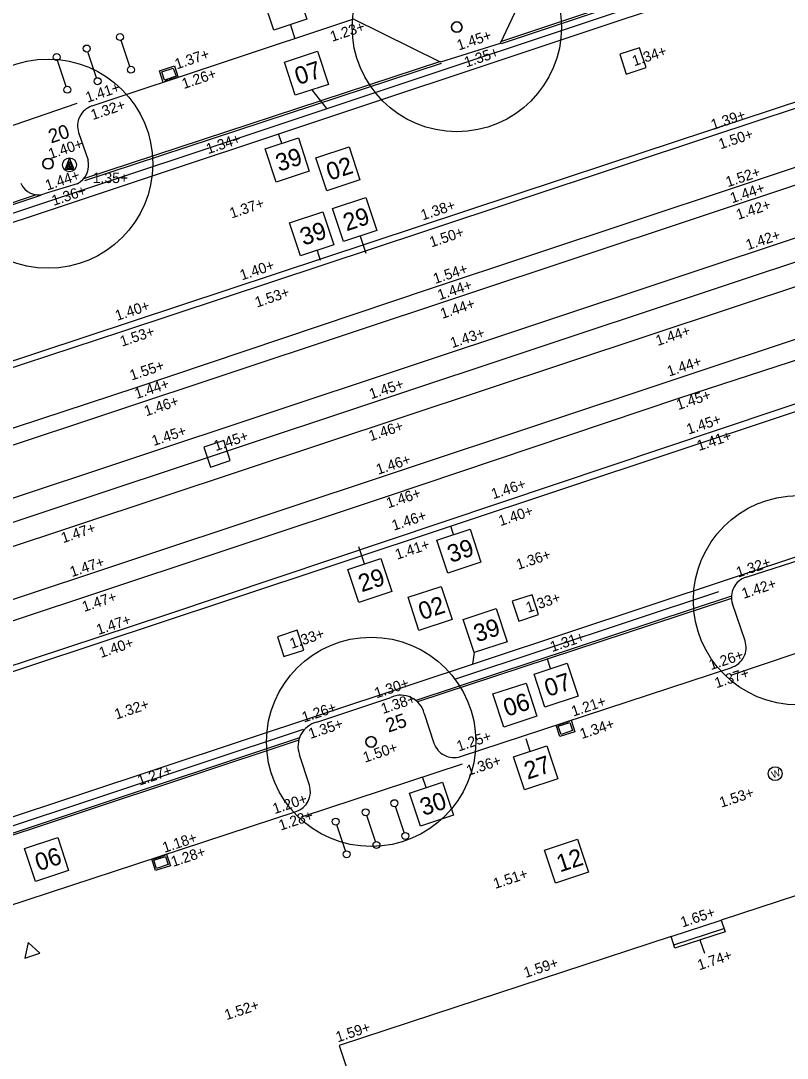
# Model space of a CAD drawing. Extents: x 122462 to 123306, y 485548 to 486417.
# Drawn here: x 122736.78 to 122758.75, y 486138.24 to 486167.98 of the extents above; entities that cross this region are included whole.
import ezdxf

# ---------------------------------------------------------------- set-up
doc = ezdxf.new("R2010")
doc.units = 0
for name, color, linetype in [('B-WE-GR-BOOM_BOOMDIAMETER', 7, 'Continuous'), ('B-WE-OG-HOOGTEPUNT-S', 7, 'Continuous'), ('B-WE-OG-TOPOGRAFIE_GEVELDETAIL-G', 7, 'Continuous'), ('B-WE-OG-TOPOKAART-G', 7, 'Continuous'), ('iba7-verkeersbord blauw', 7, 'Continuous'), ('iba7-verkeersbord rood', 7, 'Continuous'), ('V markering 1-1 10 cm', 7, 'Continuous'), ('V markering figuratie', 7, 'Continuous'), ('V markering ononderbroken streep 10 cm', 7, 'Continuous'), ('V materiaalscheiding algemeen', 7, 'Continuous'), ('V meubilair fietsenrek', 7, 'Continuous'), ('V meubilair trammast', 7, 'Continuous'), ('V meubilair verkeersbord', 7, 'Continuous'), ('V opsluitband 100x200 mm', 7, 'Continuous'), ('V Rails', 7, 'Continuous'), ('V riool putdeksel', 7, 'Continuous'), ('V riool trottoirkolk', 7, 'Continuous'), ('V RWS-band 115-225x250 mm specie', 7, 'Continuous'), ('V trottoirband 180-200x250 mm specie', 7, 'Continuous'), ('X-WE-AL-TEKENBLAD-S', 7, 'Continuous')]:
    doc.layers.add(name, color=color, linetype=linetype)

msp = doc.modelspace()

# ---------------------------------------------------------------- linework, layer by layer
at = {"layer": 'B-WE-OG-TOPOGRAFIE_GEVELDETAIL-G'}
for p, q in [((122755.498, 486141.492), (122756.934, 486141.963)), ((122756.247, 486141.632), (122756.372, 486141.253))]:
    msp.add_line(p, q, dxfattribs=at)
msp.add_lwpolyline([(122755.42, 486141.73), (122756.855, 486142.201), (122756.965, 486141.868), (122755.529, 486141.397)], close=True, dxfattribs=at)
at = {"layer": 'B-WE-OG-TOPOKAART-G'}
for points in [[(122759.037, 486142.916), (122756.856, 486142.201)], [(122755.42, 486141.73), (122749.252, 486139.707), (122745.91, 486138.61), (122746.866, 486135.726), (122744.974, 486135.1)]]:
    msp.add_lwpolyline(points, dxfattribs=at)
at = {"layer": 'iba7-verkeersbord blauw'}
msp.add_circle((122758.4, 486146.399), 0.2, dxfattribs=at)
at = {"layer": 'iba7-verkeersbord rood'}
for centre, radius in [((122749.278, 486167.803), 3), ((122749.278, 486167.803), 0.15), ((122737.564, 486163.887), 3), ((122737.564, 486163.887), 0.15), ((122759.058, 486151.369), 3), ((122746.823, 486147.311), 3), ((122746.823, 486147.311), 0.15)]:
    msp.add_circle(centre, radius, dxfattribs=at)
for centre, start, end in [((122749.278, 486167.803), 0, 180), ((122749.278, 486167.803), 180, 0), ((122737.564, 486163.887), 0, 180), ((122737.564, 486163.887), 180, 0), ((122746.823, 486147.311), 0, 180), ((122746.823, 486147.311), 180, 0)]:
    msp.add_arc(centre, 0.15, start, end, dxfattribs=at)
at = {"layer": 'V markering 1-1 10 cm'}
for p, q in [((122774.598, 486175.14), (122727.918, 486159.59)), ((122732.076, 486143.681), (122790.419, 486163.059)), ((122749.252, 486149.122), (122756.783, 486151.623)), ((122732.154, 486143.443), (122744.883, 486147.671))]:
    msp.add_line(p, q, dxfattribs=at)
msp.add_lwpolyline([(122774.677, 486174.903), (122727.997, 486159.353)], dxfattribs=at)
at = {"layer": 'V markering figuratie'}
msp.add_line((122712.845, 486143.511), (122860.885, 486192.728), dxfattribs=at)
at = {"layer": 'V markering ononderbroken streep 10 cm'}
for p, q in [((122761.511, 486171.05), (122750.527, 486167.381)), ((122748.806, 486166.818), (122738.581, 486163.449)), ((122737.222, 486162.996), (122727.575, 486159.765)), ((122757.15, 486151.423), (122748.155, 486148.454))]:
    msp.add_line(p, q, dxfattribs=at)
for points in [[(122782.506, 486173.456), (122769.669, 486169.188), (122753.621, 486163.883), (122729.113, 486155.773)], [(122728.941, 486151.077), (122760.57, 486161.6), (122777.147, 486167.134), (122788.89, 486171.042)], [(122790.431, 486167.268), (122783.519, 486164.927), (122758.686, 486156.675), (122742.703, 486151.362), (122729.592, 486147.018)], [(122744.749, 486147.36), (122732.209, 486143.188)]]:
    msp.add_lwpolyline(points, dxfattribs=at)
at = {"layer": 'V materiaalscheiding algemeen'}
for points in [[(122761.53, 486170.993), (122750.546, 486167.324)], [(122748.825, 486166.761), (122738.611, 486163.396)], [(122780.156, 486165.287), (122764.259, 486160.016), (122760.446, 486158.724), (122755.663, 486157.161), (122747.256, 486154.337), (122738.577, 486151.45), (122730.117, 486148.653), (122721.549, 486145.803), (122712.998, 486142.94), (122707.935, 486141.266)], [(122737.346, 486162.974), (122727.454, 486159.661)], [(122757.15, 486151.486), (122748.103, 486148.5)], [(122757.129, 486149.222), (122763.738, 486151.452)], [(122744.769, 486147.43), (122732.216, 486143.253), (122732.207, 486143.158)], [(122744.83, 486145.158), (122749.439, 486146.684)]]:
    msp.add_lwpolyline(points, dxfattribs=at)
at = {"layer": 'V meubilair fietsenrek'}
for p, q in [((122739.907, 486166.676), (122739.659, 486167.422)), ((122738.086, 486166.102), (122737.838, 486166.848)), ((122738.951, 486166.347), (122738.703, 486167.093)), ((122747.769, 486144.71), (122747.521, 486145.457)), ((122746.945, 486144.45), (122746.698, 486145.197)), ((122746.087, 486144.183), (122745.839, 486144.929))]:
    msp.add_line(p, q, dxfattribs=at)
for centre in [(122739.628, 486167.517), (122738.672, 486167.188), (122737.807, 486166.943), (122739.938, 486166.581), (122738.982, 486166.252), (122738.117, 486166.007), (122747.49, 486145.552), (122745.808, 486145.024), (122746.666, 486145.292), (122747.8, 486144.615), (122746.976, 486144.355), (122746.118, 486144.088)]:
    msp.add_circle(centre, 0.1, dxfattribs=at)
at = {"layer": 'V meubilair trammast'}
msp.add_lwpolyline([(122736.901, 486141.114), (122737.328, 486141.255), (122736.992, 486141.555)], close=True, dxfattribs=at)
at = {"layer": 'V meubilair verkeersbord'}
msp.add_lwpolyline([(122738.304, 486163.717), (122738.052, 486163.717), (122738.179, 486164.04), (122738.293, 486163.755), (122738.108, 486163.755), (122738.179, 486163.955), (122738.235, 486163.795), (122738.166, 486163.795), (122738.179, 486163.835), (122738.18, 486163.885)], dxfattribs=at)
msp.add_circle((122738.179, 486163.855), 0.2, dxfattribs=at)
at = {"layer": 'V opsluitband 100x200 mm'}
msp.add_lwpolyline([(122736.032, 486164.805), (122738.398, 486165.618)], dxfattribs=at)
at = {"layer": 'V Rails'}
for p, q in [((122714.919, 486148.627), (122859.557, 486196.72)), ((122715.373, 486147.26), (122860.011, 486195.354)), ((122712.39, 486144.878), (122860.43, 486194.095))]:
    msp.add_line(p, q, dxfattribs=at)
at = {"layer": 'V riool putdeksel'}
for points in [[(122753.947, 486167.024), (122754.135, 486166.454), (122754.705, 486166.642), (122754.517, 486167.212)], [(122742.029, 486155.76), (122742.217, 486155.19), (122742.787, 486155.377), (122742.599, 486155.947)], [(122751.053, 486150.77), (122751.623, 486150.958), (122751.435, 486151.528), (122750.865, 486151.34)], [(122744.324, 486149.756), (122744.894, 486149.944), (122744.706, 486150.514), (122744.136, 486150.326)]]:
    msp.add_lwpolyline(points, close=True, dxfattribs=at)
at = {"layer": 'V riool trottoirkolk'}
for p, q in [((122740.757, 486166.551), (122741.184, 486166.692)), ((122740.867, 486166.218), (122740.757, 486166.551)), ((122741.184, 486166.692), (122741.294, 486166.36)), ((122741.294, 486166.36), (122740.867, 486166.218)), ((122740.914, 486166.234), (122740.913, 486166.239)), ((122740.995, 486166.277), (122740.919, 486166.251)), ((122741.009, 486166.266), (122741.008, 486166.27)), ((122741.033, 486166.273), (122741.031, 486166.278)), ((122741.114, 486166.316), (122741.038, 486166.291)), ((122741.128, 486166.305), (122741.126, 486166.31)), ((122741.152, 486166.313), (122741.15, 486166.317)), ((122741.188, 486166.34), (122741.156, 486166.33)), ((122741.232, 486166.355), (122741.188, 486166.34)), ((122741.247, 486166.344), (122741.245, 486166.349)), ((122752.124, 486147.792), (122752.551, 486147.933)), ((122752.171, 486147.808), (122752.173, 486147.803)), ((122752.185, 486147.797), (122752.23, 486147.811)), ((122752.23, 486147.811), (122752.261, 486147.822)), ((122752.266, 486147.839), (122752.268, 486147.834)), ((122752.29, 486147.847), (122752.292, 486147.842)), ((122752.304, 486147.836), (122752.38, 486147.861)), ((122752.385, 486147.878), (122752.387, 486147.873)), ((122752.409, 486147.886), (122752.41, 486147.881)), ((122752.423, 486147.875), (122752.499, 486147.9)), ((122752.504, 486147.917), (122752.505, 486147.912)), ((122752.551, 486147.933), (122752.661, 486147.6)), ((122752.233, 486147.46), (122752.124, 486147.792)), ((122752.661, 486147.6), (122752.233, 486147.46)), ((122740.534, 486143.951), (122740.962, 486144.091)), ((122740.643, 486143.618), (122740.534, 486143.951)), ((122740.582, 486143.966), (122740.583, 486143.961)), ((122740.596, 486143.955), (122740.641, 486143.97)), ((122740.641, 486143.97), (122740.672, 486143.98)), ((122740.677, 486143.997), (122740.678, 486143.993)), ((122740.701, 486144.005), (122740.702, 486144)), ((122740.715, 486143.994), (122740.791, 486144.019)), ((122740.796, 486144.036), (122740.797, 486144.031)), ((122740.819, 486144.044), (122740.821, 486144.039)), ((122740.833, 486144.033), (122740.91, 486144.058)), ((122740.914, 486144.075), (122740.916, 486144.07)), ((122740.962, 486144.091), (122741.071, 486143.758)), ((122741.071, 486143.758), (122740.643, 486143.618))]:
    msp.add_line(p, q, dxfattribs=at)
for points in [[(122740.82, 486166.519), (122741.152, 486166.629), (122741.231, 486166.392), (122740.899, 486166.282)], [(122752.597, 486147.632), (122752.265, 486147.523), (122752.187, 486147.76), (122752.519, 486147.87)], [(122741.008, 486143.79), (122740.675, 486143.681), (122740.597, 486143.919), (122740.93, 486144.028)]]:
    msp.add_lwpolyline(points, close=True, dxfattribs=at)
for centre, start, end in [((122740.922, 486166.242), 108.3322, 198.3322), ((122740.998, 486166.267), 18.3322, 108.3322), ((122741.041, 486166.281), 108.3322, 198.3322), ((122741.117, 486166.306), 18.3322, 108.3322), ((122741.16, 486166.321), 108.3322, 198.3322), ((122741.236, 486166.346), 18.3322, 108.3322), ((122752.182, 486147.806), 198.1886, 288.1886), ((122752.258, 486147.831), 288.1886, 18.1886), ((122752.301, 486147.845), 198.1886, 288.1886), ((122752.377, 486147.87), 288.1886, 18.1886), ((122752.42, 486147.884), 198.1886, 288.1886), ((122752.496, 486147.909), 288.1886, 18.1886), ((122740.593, 486143.965), 198.1247, 288.1247), ((122740.669, 486143.989), 288.1247, 18.1247), ((122740.712, 486144.003), 198.1247, 288.1247), ((122740.788, 486144.028), 288.1247, 18.1247), ((122740.83, 486144.042), 198.1247, 288.1247), ((122740.906, 486144.067), 288.1247, 18.1247)]:
    msp.add_arc(centre, 0.01, start, end, dxfattribs=at)
at = {"layer": 'V RWS-band 115-225x250 mm specie'}
msp.add_lwpolyline([(122788.059, 486166.632), (122787.124, 486166.306), (122785.206, 486165.623), (122777.128, 486162.968), (122760.015, 486157.342), (122740.955, 486150.951), (122719.987, 486144.031), (122708.301, 486140.155)], dxfattribs=at)
at = {"layer": 'V trottoirband 180-200x250 mm specie'}
msp.add_line((122757.538, 486150.208), (122757.18, 486151.27), dxfattribs=at)
for points in [[(122802.843, 486178.897), (122803.005, 486178.403), (122796.653, 486176.321), (122790.145, 486174.137), (122787.981, 486173.414), (122783.643, 486171.985), (122782.562, 486171.633), (122774.188, 486168.85), (122765.631, 486166.001), (122757.287, 486163.217), (122748.482, 486160.287), (122740.076, 486157.459), (122731.818, 486154.747)], [(122772.234, 486176.591), (122764.613, 486174.078), (122763.348, 486171.596), (122761.53, 486170.993), (122760.929, 486172.847), (122759.643, 486172.424), (122751.679, 486169.79), (122750.518, 486167.331), (122748.806, 486166.796), (122746.321, 486168.026), (122738.818, 486165.54)], [(122731.297, 486156.319), (122739.679, 486159.075), (122748.36, 486161.956), (122756.611, 486164.69), (122764.995, 486167.464)], [(122738.439, 486164.777), (122738.709, 486163.983)], [(122738.402, 486163.308), (122737.452, 486163.018)], [(122757.567, 486152.034), (122759.417, 486152.622), (122761.652, 486153.364)], [(122749.383, 486146.892), (122757.155, 486149.446)], [(122745.268, 486147.876), (122747.383, 486148.585)], [(122748.346, 486148.122), (122748.622, 486147.275)], [(122745.052, 486146.07), (122744.767, 486146.939)], [(122733.81, 486141.749), (122740.748, 486144.02), (122744.67, 486145.313)]]:
    msp.add_lwpolyline(points, dxfattribs=at)
for centre, radius, start, end in [((122739.007, 486164.971), 0.6, 108.3322, 198.7713), ((122738.126, 486163.841), 0.6, 297.3747, 13.7118), ((122737.285, 486163.541), 0.549, 203.3042, 287.6664), ((122757.749, 486151.462), 0.6, 107.6439, 198.6036), ((122756.969, 486150.016), 0.6, 288.01, 18.6036), ((122747.674, 486147.957), 0.692, 13.8151, 114.8294), ((122745.444, 486147.18), 0.718, 104.1614, 199.5731), ((122749.193, 486147.461), 0.6, 198.0639, 288.4796), ((122744.482, 486145.883), 0.6, 288.2477, 18.1882)]:
    msp.add_arc(centre, radius, start, end, dxfattribs=at)
at = {"layer": 'X-WE-AL-TEKENBLAD-S'}
for p, q in [((122744.508, 486167.87), (122744.64, 486167.469)), ((122745.123, 486166.004), (122745.539, 486165.472)), ((122744.262, 486164.467), (122744.171, 486164.741)), ((122746.507, 486161.811), (122746.669, 486161.321)), ((122745.274, 486161.399), (122745.364, 486161.125)), ((122749.182, 486153.254), (122749.104, 486153.49)), ((122746.63, 486152.412), (122746.468, 486152.901)), ((122749.773, 486149.869), (122749.731, 486149.541)), ((122751.967, 486149.412), (122751.877, 486149.686)), ((122751.381, 486147.039), (122751.262, 486147.398)), ((122748.395, 486145.999), (122748.294, 486146.305))]:
    msp.add_line(p, q, dxfattribs=at)
for points in [[(122743.719, 486168.663), (122744.669, 486168.977), (122744.982, 486168.027), (122744.033, 486167.714)], [(122744.335, 486166.797), (122745.285, 486167.11), (122745.598, 486166.16), (122744.649, 486165.847)], [(122743.787, 486164.31), (122744.737, 486164.623), (122745.05, 486163.674), (122744.1, 486163.36)], [(122745.24, 486164.055), (122746.19, 486164.368), (122746.503, 486163.419), (122745.553, 486163.105)], [(122745.719, 486162.604), (122746.668, 486162.917), (122746.982, 486161.967), (122746.032, 486161.654)], [(122744.486, 486162.192), (122745.435, 486162.505), (122745.749, 486161.556), (122744.799, 486161.242)], [(122748.707, 486153.097), (122749.657, 486153.411), (122749.97, 486152.461), (122749.021, 486152.148)], [(122746.155, 486152.255), (122747.105, 486152.568), (122747.418, 486151.619), (122746.468, 486151.305)], [(122747.88, 486151.455), (122748.83, 486151.769), (122749.143, 486150.819), (122748.194, 486150.506)], [(122749.459, 486150.819), (122750.409, 486151.132), (122750.722, 486150.182), (122749.773, 486149.869)], [(122751.492, 486149.255), (122752.442, 486149.568), (122752.755, 486148.619), (122751.805, 486148.305)], [(122750.312, 486148.684), (122751.261, 486148.998), (122751.575, 486148.048), (122750.625, 486147.735)], [(122750.906, 486146.882), (122751.856, 486147.196), (122752.169, 486146.246), (122751.219, 486145.933)], [(122747.92, 486145.842), (122748.87, 486146.156), (122749.183, 486145.206), (122748.233, 486144.893)], [(122736.891, 486144.256), (122737.841, 486144.57), (122738.154, 486143.62), (122737.205, 486143.307)], [(122751.788, 486144.208), (122752.738, 486144.521), (122753.051, 486143.572), (122752.102, 486143.258)]]:
    msp.add_lwpolyline(points, close=True, dxfattribs=at)

# ---------------------------------------------------------------- texts
at = {"layer": 'B-WE-GR-BOOM_BOOMDIAMETER'}
for s, rotation, p in [('20', 18.3322, (122737.65, 486164.463)), ('25', 18.8399, (122747.318, 486147.573))]:
    msp.add_text(s, height=0.4, rotation=rotation, dxfattribs=at).set_placement(p)
at = {"layer": 'B-WE-OG-HOOGTEPUNT-S'}
for s, rotation, p in [('1.23+', 18.4074, (122745.706, 486167.378)), ('1.45+', 18.4074, (122749.338, 486167.13)), ('1.35+', 18.4074, (122749.547, 486166.642)), ('1.34+', 18.4074, (122754.36, 486166.678)), ('1.37+', 18.5166, (122741.254, 486166.589)), ('1.26+', 18.5166, (122741.455, 486166.026)), ('1.41+', 18.5166, (122738.696, 486165.634)), ('1.32+', 18.5166, (122738.845, 486165.134)), ('1.39+', 18.3718, (122756.617, 486164.85)), ('1.50+', 18.3718, (122756.838, 486164.297)), ('1.40+', 18.5166, (122737.631, 486164.016)), ('1.34+', 18.5166, (122742.152, 486164.158)), ('1.44+', 18.5166, (122737.541, 486163.115)), ('1.52+', 18.3429, (122757.044, 486163.21)), ('1.44+', 18.3429, (122757.168, 486162.75)), ('1.36+', 18.4074, (122737.726, 486162.676)), ('1.37+', 18.5166, (122742.824, 486162.313)), ('1.38+', 18.3718, (122748.302, 486162.26)), ('1.42+', 18.3429, (122757.342, 486162.275)), ('1.50+', 18.3718, (122748.55, 486161.485)), ('1.42+', 18.3429, (122757.619, 486161.405)), ('1.40+', 18.5166, (122743.118, 486160.538)), ('1.54+', 18.3718, (122748.657, 486160.436)), ('1.53+', 18.5166, (122743.551, 486159.761)), ('1.44+', 18.3718, (122748.784, 486159.971)), ('1.40+', 18.3718, (122739.543, 486159.378)), ('1.44+', 18.3718, (122748.863, 486159.435)), ('1.53+', 18.3718, (122739.682, 486158.639)), ('1.43+', 18.3718, (122749.147, 486158.597)), ('1.44+', 18.3429, (122755.036, 486158.66)), ('1.44+', 18.3429, (122755.36, 486157.781)), ('1.55+', 18.3718, (122739.96, 486157.667)), ('1.44+', 18.3718, (122740.102, 486157.137)), ('1.45+', 18.3718, (122746.825, 486157.132)), ('1.45+', 18.3429, (122755.625, 486156.821)), ('1.46+', 18.3718, (122740.375, 486156.642)), ('1.46+', 18.3718, (122746.81, 486155.929)), ('1.45+', 18.3429, (122755.919, 486156.119)), ('1.45+', 18.3718, (122740.592, 486155.789)), ('1.45+', 18.3718, (122742.37, 486155.643)), ('1.41+', 18.3429, (122756.216, 486155.647)), ('1.46+', 18.3718, (122747.023, 486154.968)), ('1.46+', 18.3738, (122750.323, 486154.266)), ('1.46+', 18.3718, (122747.314, 486154.003)), ('1.46+', 18.3718, (122747.473, 486153.362)), ('1.40+', 18.3738, (122750.529, 486153.494)), ('1.47+', 18.4023, (122737.994, 486153.005)), ('1.41+', 18.3718, (122747.568, 486152.53)), ('1.47+', 18.4023, (122738.246, 486152.032)), ('1.36+', 18.3738, (122751.038, 486152.242)), ('1.32+', 18.3738, (122757.341, 486152.018)), ('1.42+', 18.3738, (122757.501, 486151.41)), ('1.47+', 18.4023, (122738.596, 486151.033)), ('1.33+', 18.3738, (122751.315, 486151.01)), ('1.47+', 18.4023, (122739.006, 486150.374)), ('1.33+', 18.3738, (122744.547, 486149.975)), ('1.40+', 18.4023, (122739.08, 486149.714)), ('1.31+', 18.3738, (122752.009, 486149.883)), ('1.26+', 18.3738, (122756.56, 486149.365)), ('1.37+', 18.3738, (122756.723, 486148.846)), ('1.30+', 18.3738, (122746.975, 486148.556)), ('1.32+', 18.3738, (122739.525, 486147.95)), ('1.26+', 18.3738, (122744.896, 486147.863)), ('1.38+', 18.3738, (122747.162, 486148.109)), ('1.21+', 18.3738, (122752.617, 486148.034)), ('1.35+', 18.3738, (122745.083, 486147.392)), ('1.34+', 18.3738, (122752.862, 486147.389)), ('1.25+', 18.3738, (122749.332, 486147.033)), ('1.50+', 18.3738, (122746.646, 486146.713)), ('1.36+', 18.3738, (122749.611, 486146.334)), ('1.27+', 18.3738, (122740.183, 486146.053)), ('1.20+', 18.3738, (122744.057, 486145.239)), ('1.53+', 18.1571, (122756.858, 486145.421)), ('1.28+', 18.3738, (122744.23, 486144.763)), ('1.18+', 18.3738, (122740.898, 486144.126)), ('1.28+', 18.3738, (122741.144, 486143.723)), ('1.51+', 18.2074, (122750.379, 486143.093)), ('1.65+', 18.1571, (122755.746, 486141.988)), ('1.74+', 18.1571, (122756.231, 486140.76)), ('1.59+', 18.2074, (122751.252, 486140.541)), ('1.52+', 18.2074, (122742.679, 486139.33)), ('1.59+', 18.2074, (122745.866, 486138.694))]:
    msp.add_text(s, height=0.3, rotation=rotation, dxfattribs=at).set_placement(p)
msp.add_text('1.35+', height=0.3, dxfattribs=at).set_placement((122738.844, 486163.331))
at = {"layer": 'iba7-verkeersbord blauw'}
msp.add_text('W', height=0.2, rotation=18.1571, dxfattribs=at).set_placement((122758.332, 486146.266))
at = {"layer": 'X-WE-AL-TEKENBLAD-S'}
for s, p in [('07', (122744.733, 486166.138)), ('39', (122744.185, 486163.651)), ('02', (122745.638, 486163.397)), ('29', (122746.117, 486161.945)), ('39', (122744.884, 486161.533)), ('39', (122749.105, 486152.439)), ('29', (122746.553, 486151.597)), ('02', (122748.278, 486150.797)), ('39', (122749.857, 486150.16)), ('07', (122751.89, 486148.597)), ('06', (122750.71, 486148.026)), ('27', (122751.305, 486146.224)), ('30', (122748.319, 486145.184)), ('06', (122737.29, 486143.598)), ('12', (122752.234, 486143.565))]:
    msp.add_text(s, height=0.5, rotation=18.2603, dxfattribs=at).set_placement(p)

doc.saveas('drawing.dxf')
